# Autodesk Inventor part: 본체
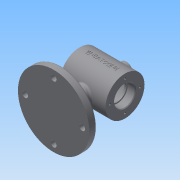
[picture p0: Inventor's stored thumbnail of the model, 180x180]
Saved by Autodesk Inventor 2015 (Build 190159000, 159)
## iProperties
Created: 2018-12
Part Number: 본체
Material: 일반
Document SubType Name: Modeling
Designer: 405-15
Density: 1 g/cm^3
Appearance: 기본값
Author: 405-15
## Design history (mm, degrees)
sketch "스케치1"
  geometry: C1 r 55 at (0, 0); 1 further point
  constraints: 1 centre point, 1 coincident
  dimensions: "d0" = 110 diameter of C1
extrude "돌출1" new body sketch "스케치1" distance "d1" = 11; taper "d2" = 0 deg
sketch "스케치2"
  geometry: L1 (0, 11)-(0, 25.737); L2 (0, 25.737)-(55, 11); L3 (55, 11)-(-55, 11) reference; L4 (0, 11)-(55, 11); 1 further point
  constraints: 7 end point, 1 collinear, 1 midpoint, 1 point on line, 1 vertical
  dimensions: "d4" = 15 deg angle of L3 L2
revolve "회전1" sketch "스케치2" stored, may be unused: angle "d5" = 90 deg
sketch "스케치3"
  geometry: L1 (0, 0)-(75, 0); C1 r 30 at (75, 0)
  constraints: 2 end point, 1 centre point, 1 coincident, 1 horizontal
  dimensions: "d6" = 75 distance of L1.start L1.end; "d7" = 60 diameter of C1
extrude "돌출2" join sketch "스케치3" stored distance "d8" = 70; taper "d9" = 0 deg
sketch "스케치4"
  geometry: C1 r 12 at (0, 0); 1 further point
  constraints: 1 centre point, 1 coincident
  dimensions: "d10" = 24 diameter of C1
extrude "돌출3" join sketch "스케치4" stored distance "d11" = 70; taper "d12" = 0 deg
sketch "스케치5"
  geometry: C1 r 30 at (0, 0) reference; C2 r 16 at (0, 0); 1 further point
  constraints: 1 centre point, 1 coincident
  dimensions: "d14" = 32 diameter of C2
extrude "돌출4" cut sketch "스케치5" distance "d15" = 12; taper "d16" = 0 deg
sketch "스케치6"
  geometry: C1 r 16 at (0, 0) reference; C2 r 14 at (0, 0); 1 further point
  constraints: 1 centre point, 1 coincident
  dimensions: "d17" = 28 diameter of C2
extrude "돌출5" cut sketch "스케치6" distance "d18" = 3; taper "d19" = 0 deg
sketch "스케치7"
  geometry: C1 r 14 at (0, 0) reference; C2 r 25 at (0, 0); 1 further point
  constraints: 1 centre point, 1 coincident
  dimensions: "d20" = 50 diameter of C2
extrude "돌출6" cut sketch "스케치7" distance "d21" = 40; taper "d22" = 0 deg
node "작업 평면1"
sketch "스케치8"
  geometry: C1 r 10 at (0, 0); 1 further point
  constraints: 1 centre point, 1 coincident
  dimensions: "d24" = 20 diameter of C1
extrude "돌출7" join sketch "스케치8" stored distance "d25" = 40; taper "d26" = 0 deg
sketch "스케치9"
  geometry: C1 r 5 at (0, 0); 1 further point
  constraints: 1 centre point, 1 coincident
  dimensions: "d27" = 10 diameter of C1
extrude "돌출8" cut sketch "스케치9" stored distance "d28" = 40; taper "d29" = 0 deg
sketch "스케치10" dims "d31" = 46
  geometry: C1 r 30 at (0, 0) reference; 3 further points
  constraints: 1 coincident, 1 vertical alignment, 2 other
hole "구멍1" sketch "스케치10" at (0, 23) diameter "d32" = 3.242; stored, may be unused: countersink angle "d36" = 90 deg, drill point angle "d38" = 118 deg; dims "d33" = 8, "d34" = 4, "d35" = 2, "d37" = 10
fillet "모깎기1" dims "d42" = 0.3
fillet "모깎기2" dims "d43" = 3
fillet "모깎기3" dims "d44" = 3
chamfer "모따기1" distance "d45" = 1; stored, may be unused: second distance "d46" = 2, angle "d47" = 45 deg
sketch "스케치11" dims "d48" = 88
  geometry: C1 r 6 at (0, 0) reference; 3 further points
  constraints: 1 coincident, 1 vertical alignment, 2 other
hole "구멍2" sketch "스케치11" at (0, 44) diameter "d50" = 9; stored, may be unused: countersink angle "d54" = 90 deg, drill point angle "d56" = 0 deg; dims "d51" = 8, "d52" = 4, "d53" = 2, "d55" = 10
hole "구멍3" diameter "d59" = 14; stored, may be unused: countersink angle "d63" = 90 deg, drill point angle "d65" = 0 deg; dims "d57" = 10, "d58" = 10, "d60" = 8, "d61" = 4, "d62" = 2, "d64" = 10
node "작업 평면2"
sketch "스케치12"
  geometry: L1 (-35, 105)-(-35, 45) reference; L2 (-35, 105)-(35, 105) reference; L3 (-24.887, 78.602)-(24.887, 78.602); L4 (24.887, 78.602)-(24.887, 71.398); L5 (24.887, 71.398)-(-24.887, 71.398); L6 (-24.887, 71.398)-(-24.887, 78.602); L7 (0, 78.602)-(0, 71.398); L8 (0, 75)-(-24.887, 75); 1 further point
  constraints: 4 end point, 4 midpoint, 2 other
  dimensions: "d70" = 35 distance from line of L8.start L1; "d71" = 30 distance from line of L8.start L2
feature "엠보싱1" sketch "스케치12" dims "d72" = 0.5, "d73" = 0
node "솔리드1"
mirror "대칭1"
pattern_circular "원형 패턴1" dims angle "d40" = 360 deg
mirror "대칭2"
pattern_circular "원형 패턴2" dims angle "d67" = 360 deg
other parameters: "d23" = -112
